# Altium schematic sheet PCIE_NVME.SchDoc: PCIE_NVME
size A3; Author: Silvio Navaretti; CompanyName: ARDUINO; Organization: ARDUINO; SheetNumber: 27; SheetTotal: 51; RevAuthor: Silvio Navaretti
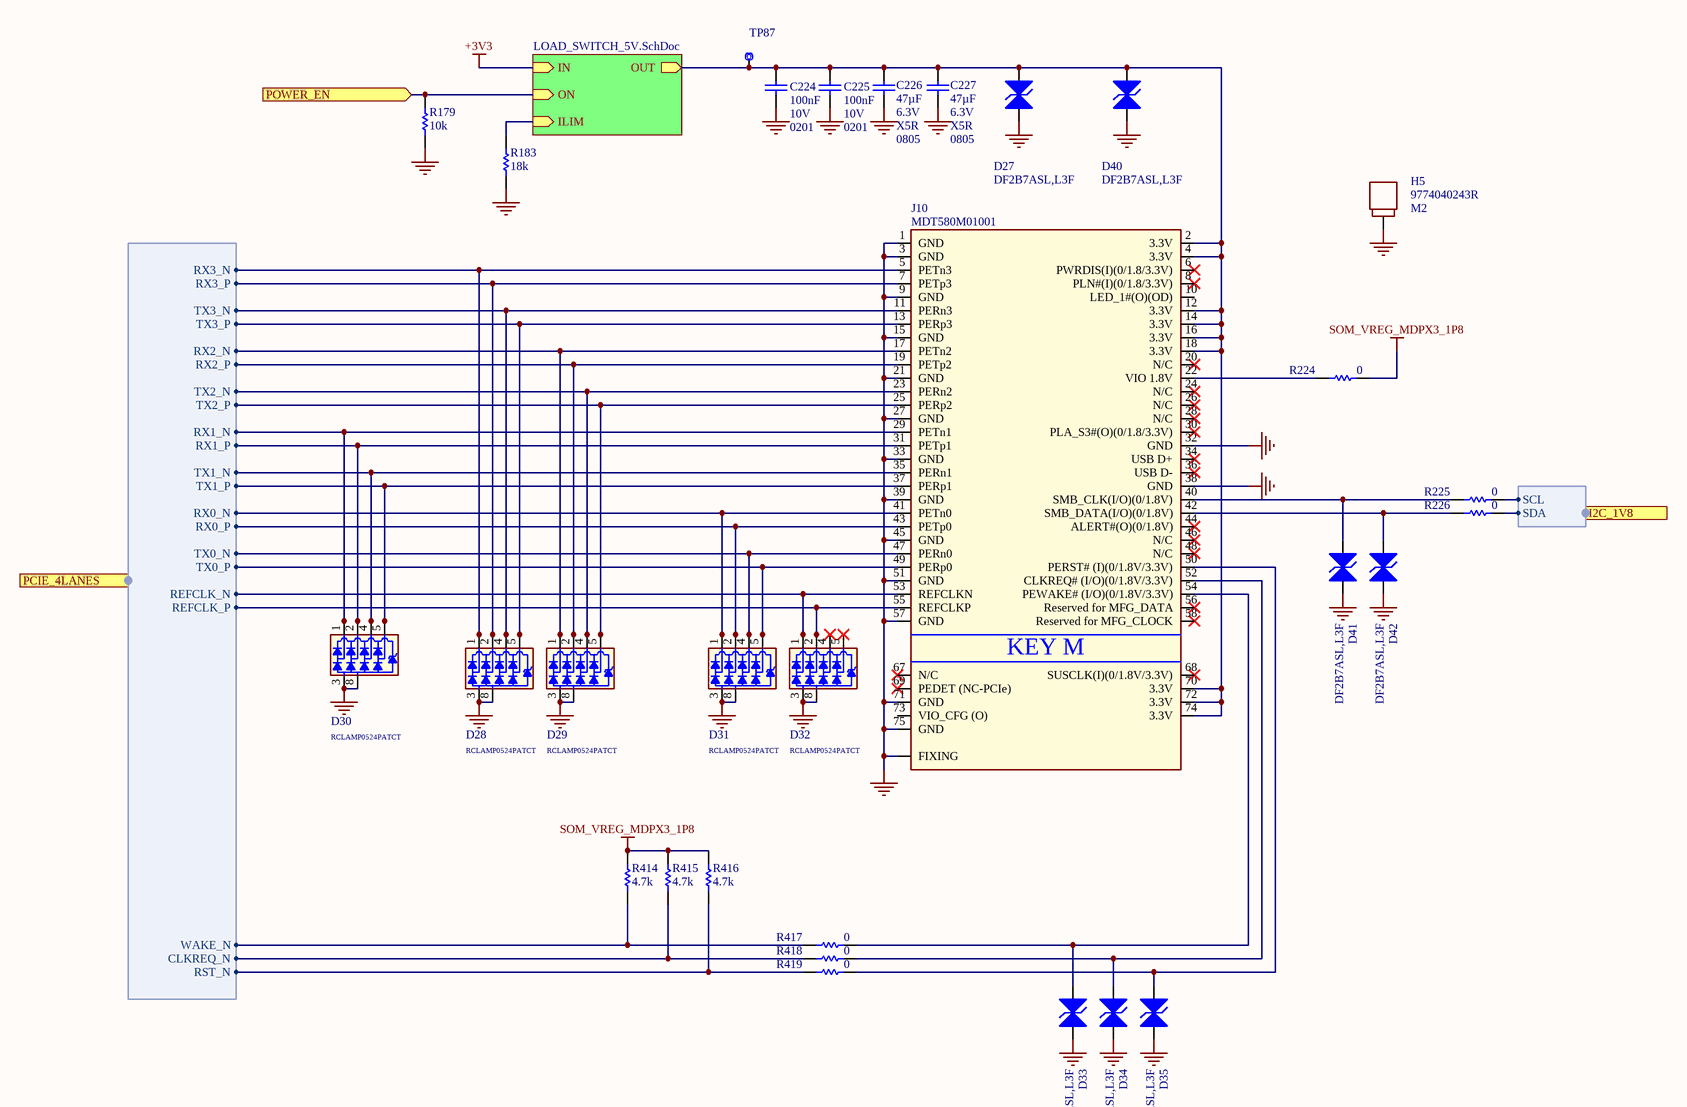
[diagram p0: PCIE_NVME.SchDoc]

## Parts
C224  value 100nF  Voltage: 10V  Case Code (Imperial): 0201  [CAP-0201]  (hidden comment: CL03A104KP3NNNC)
C225  value 100nF  Voltage: 10V  Case Code (Imperial): 0201  [CAP-0201]  (hidden comment: CL03A104KP3NNNC)
C226  value 47µF  Voltage: 6.3V  Dielectric: X5R  Case Code (Imperial): 0805  [CAP-0805]  (hidden comment: C0805C476M9PAC7800)
C227  value 47µF  Voltage: 6.3V  Dielectric: X5R  Case Code (Imperial): 0805  [CAP-0805]  (hidden comment: C0805C476M9PAC7800)
D27  DF2B7ASL,L3F  [DF2B7ASL,L3F]
D28  RCLAMP0524PATCT  [SLP2510P8]
D29  RCLAMP0524PATCT  [SLP2510P8]
D30  RCLAMP0524PATCT  [SLP2510P8]
D31  RCLAMP0524PATCT  [SLP2510P8]
D32  RCLAMP0524PATCT  [SLP2510P8]
D33  DF2B7ASL,L3F  [DF2B7ASL,L3F]
D34  DF2B7ASL,L3F  [DF2B7ASL,L3F]
D35  DF2B7ASL,L3F  [DF2B7ASL,L3F]
D40  DF2B7ASL,L3F  [DF2B7ASL,L3F]
D41  DF2B7ASL,L3F  [DF2B7ASL,L3F]
D42  DF2B7ASL,L3F  [DF2B7ASL,L3F]
H5  9774040243R  [9774040243R]
J10  MDT580M01001  [MDT580M01001]
R179  value 10k  [RES-0201]  (hidden comment: RC0201FR-0710KL)
R183  value 18k  [RES-0201]  (hidden comment: RC0201FR-0718KL)
R224  value 0  [RES-0201]  (hidden comment: CRCW02010000Z0ED)
R225  value 0  [RES-0201]  (hidden comment: CRCW02010000Z0ED)
R226  value 0  [RES-0201]  (hidden comment: CRCW02010000Z0ED)
R414  value 4.7k  [RES-0201]  (hidden comment: RC0201FR-074K7L)
R415  value 4.7k  [RES-0201]  (hidden comment: RC0201FR-074K7L)
R416  value 4.7k  [RES-0201]  (hidden comment: RC0201FR-074K7L)
R417  value 0  [RES-0201]  (hidden comment: CRCW02010000Z0ED)
R418  value 0  [RES-0201]  (hidden comment: CRCW02010000Z0ED)
R419  value 0  [RES-0201]  (hidden comment: CRCW02010000Z0ED)
TP87  Test point 1.00mm  [TP-1.00MM]  (value not drawn)  (no BOM)

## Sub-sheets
U_LOAD_SWITCH_5V = LOAD_SWITCH_5V.SchDoc: IN (in), OUT (out), ON (in), ILIM (in)

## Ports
I2C_1V8 (harness I2C), PCIE_4LANES (in, harness SOM_MD_PCIE1), POWER_EN (in)

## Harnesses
SOM_MD_PCIE1: RX0_N, RX0_P, TX0_P, TX0_N, RX1_N, RX1_P, TX1_P, TX1_N, REFCLK_N, REFCLK_P, RX2_N, RX2_P, TX2_P, TX2_N, RX3_N, RX3_P, TX3_P, TX3_N, WAKE_N, CLKREQ_N, RST_N
I2C: SDA, SCL

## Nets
GND: C224.1 C225.1 C226.1 C227.1 D27.1(A1) D28.3 D28.8 D29.3 D29.8 D30.3 D30.8 D31.3 D31.8 D32.3 D32.8 D33.1(A1) D34.1(A1) D35.1(A1) D40.1(A1) D41.1(A1) D42.1(A1) H5.1 J10.1(GND) J10.3(GND) J10.9(GND) J10.15(GND) J10.21(GND) J10.27(GND) J10.32(GND) J10.33(GND) J10.38(GND) J10.39(GND) J10.45(GND) J10.51(GND) J10.57(GND) J10.71(GND) J10.75(GND) J10.FIXING R179.1 R183.1
SOM_VREG_MDPX3_1P8: R224.1 R414.2 R415.2 R416.2
POWER_EN: R179.2 ; port POWER_EN, sheet U_LOAD_SWITCH_5V/ON
NetC224_2: C224.2 C225.2 C226.2 C227.2 D27.2(A2) D40.2(A2) J10.2(3.3V) J10.4(3.3V) J10.12(3.3V) J10.14(3.3V) J10.16(3.3V) J10.18(3.3V) J10.70(3.3V) J10.72(3.3V) J10.74(3.3V) TP87.X ; sheet U_LOAD_SWITCH_5V/OUT
NetD28_1: D28.1 D28.10 J10.5(PETn3) ; port PCIE_4LANES.RX3_N
NetD28_2: D28.2 D28.9 J10.7(PETp3) ; port PCIE_4LANES.RX3_P
NetD28_4: D28.4 D28.7 J10.11(PERn3) ; port PCIE_4LANES.TX3_N
NetD28_5: D28.5 D28.6 J10.13(PERp3) ; port PCIE_4LANES.TX3_P
NetD29_1: D29.1 D29.10 J10.17(PETn2) ; port PCIE_4LANES.RX2_N
NetD29_2: D29.2 D29.9 J10.19(PETp2) ; port PCIE_4LANES.RX2_P
NetD29_4: D29.4 D29.7 J10.23(PERn2) ; port PCIE_4LANES.TX2_N
NetD29_5: D29.5 D29.6 J10.25(PERp2) ; port PCIE_4LANES.TX2_P
NetD30_1: D30.1 D30.10 J10.29(PETn1) ; port PCIE_4LANES.RX1_N
NetD30_2: D30.2 D30.9 J10.31(PETp1) ; port PCIE_4LANES.RX1_P
NetD30_4: D30.4 D30.7 J10.35(PERn1) ; port PCIE_4LANES.TX1_N
NetD30_5: D30.5 D30.6 J10.37(PERp1) ; port PCIE_4LANES.TX1_P
NetD31_1: D31.1 D31.10 J10.41(PETn0) ; port PCIE_4LANES.RX0_N
NetD31_2: D31.2 D31.9 J10.43(PETp0) ; port PCIE_4LANES.RX0_P
NetD31_4: D31.4 D31.7 J10.47(PERn0) ; port PCIE_4LANES.TX0_N
NetD31_5: D31.5 D31.6 J10.49(PERp0) ; port PCIE_4LANES.TX0_P
NetD32_1: D32.1 D32.10 J10.53(REFCLKN) ; port PCIE_4LANES.REFCLK_N
NetD32_2: D32.2 D32.9 J10.55(REFCLKP) ; port PCIE_4LANES.REFCLK_P
NetD32_4: D32.4 D32.7
NetD32_5: D32.5 D32.6
NetD33_2: D33.2(A2) J10.54(PEWAKE#_(I/O)(0/1.8V/3.3V)) R417.1
NetD34_2: D34.2(A2) J10.52(CLKREQ#_(I/O)(0/1.8V/3.3V)) R418.1
NetD35_2: D35.2(A2) J10.50(PERST#_(I)(0/1.8V/3.3V)) R419.1
NetD41_2: D41.2(A2) J10.40(SMB_CLK(I/O)(0/1.8V)) R225.2
NetD42_2: D42.2(A2) J10.42(SMB_DATA(I/O)(0/1.8V)) R226.2
NetJ10_22: J10.22(VIO_1.8V) R224.2
NetR183_2: R183.2 ; sheet U_LOAD_SWITCH_5V/ILIM
NetR225_1: R225.1 ; port I2C_1V8.SCL
NetR226_1: R226.1 ; port I2C_1V8.SDA
NetR414_1: R414.1 R417.2 ; port PCIE_4LANES.WAKE_N
NetR415_1: R415.1 R418.2 ; port PCIE_4LANES.CLKREQ_N
NetR416_1: R416.1 R419.2 ; port PCIE_4LANES.RST_N

Not connected (* = marked no-connect by the designer): J10 6(PWRDIS(I)(0/1.8/3.3V))* 8(PLN#(I)(0/1.8/3.3V))* 10(LED_1#(O)(OD)) 20(N/C)* 24(N/C)* 26(N/C)* 28(N/C)* 30(PLA_S3#(O)(0/1.8/3.3V))* 34(USB_D+)* 36(USB_D-)* 44(ALERT#(O)(0/1.8V))* 46(N/C)* 48(N/C)* 56(Reserved_for_MFG_DATA)* 58(Reserved_for_MFG_CLOCK)* 67(N/C)* 68(SUSCLK(I)(0/1.8V/3.3V))* 69(PEDET_(NC-PCIe))* 73(VIO_CFG_(O))

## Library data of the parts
C224 C225 = C0113-A.6: CAP CHIP 0201 100nF 10% 10V X5R; Manufacturer: Samsung Electro-Mechanics; Code Arduino: C0113
C226 C227 = C0199-A.1: CAP CHIP 0805 47uF 20% 6.3V X5R; Manufacturer: KEMET; Code Arduino: C0199
D27 D33-D35 D40-D42 = D0099-5: TVS BIDIRECTIONAL SMD Vr 5.5V, Vbr min 5.8V, 0.62x0.32mm; Manufacturer: TOSHIBA; Vforward max: 0V; Ireverse max: 1µA; Power max: 80W; Code Arduino: D0099; Vreverse max: 20V
D28-D32 = D0097-A.6: TVS UNIDIRECTIONAL 4CH 0.8pF 5V SLP2510P8 10-pin 2.5x1.0x0.58mm; Manufacturer: SEMTECH; Code Arduino: D0097; Device Type: ESD protection
H5 = S0074-A.2: M2 SPACER SMT ROUND STEEL H=4mm; Manufacturer: Wurth Elektronik; Code Arduino: S0074
J10 = J0573-A.2: CONN PCIE-based M.2 NGFF, KEY M, heigth 5.8mm board heigth 4.14mm gold plated, TOP MOUNT; Manufacturer: Amphenol; Code Arduino: J0573
R179 = R0145-A.21: RES CHIP 0201 10k 1% 1/20W; Manufacturer: Yageo; Power: 50mW; Temperature coefficient: 200ppm; Code Arduino: R0145
R183 = R0399-A.1: RES CHIP 0201 18k 1% 1/20W; Manufacturer: YAGEO; Power: 50mW; Code Arduino: R0399; Temperature Coefficient: 200ppm
R224-R226 R417-R419 = R0140-A.21: RES CHIP 0201 0R; Manufacturer: Vishay; Temperature coefficient: 0ppm; Code Arduino: R0140; Power: 50mW; Tolerance: 0%
R414-R416 = R0151-A.21: RES CHIP 0201 4k7 1% 1/20W; Manufacturer: Yageo; Temperature coefficient: 200ppm; Power: 50mW; Code Arduino: A5521
TP87 = UT0013-A.6: Part Number: This is not a component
